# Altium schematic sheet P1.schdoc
size 127 x 101 mm
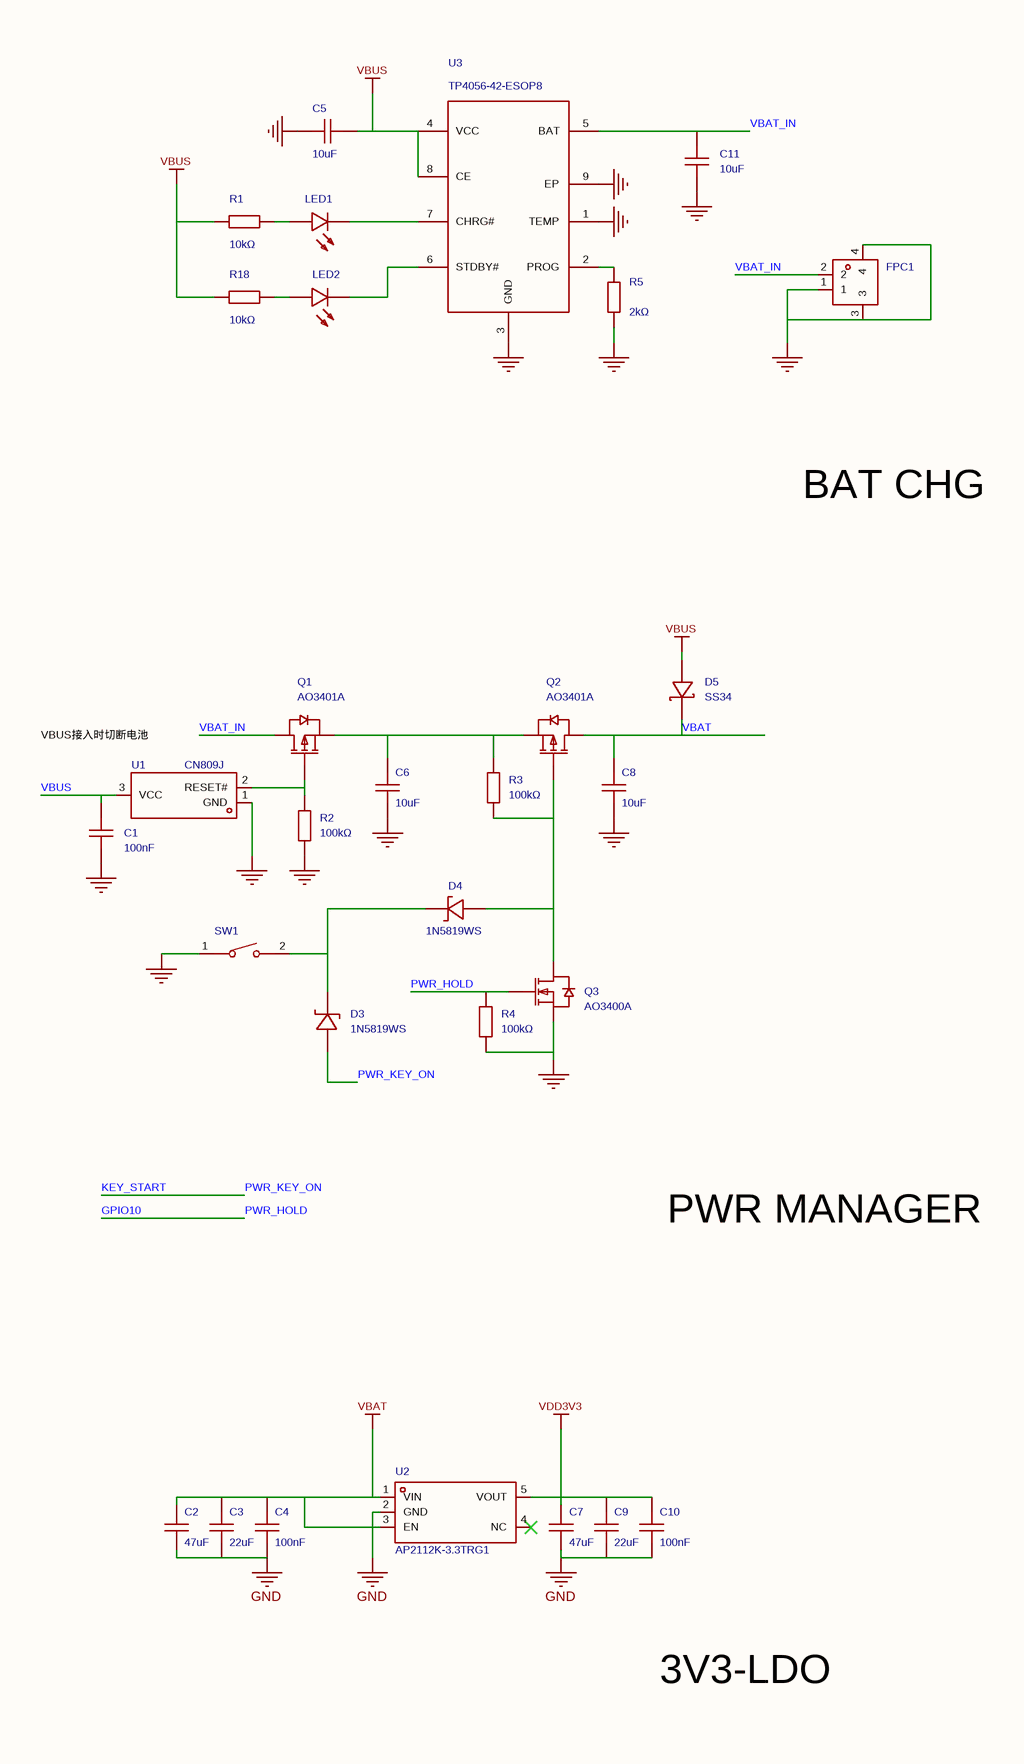
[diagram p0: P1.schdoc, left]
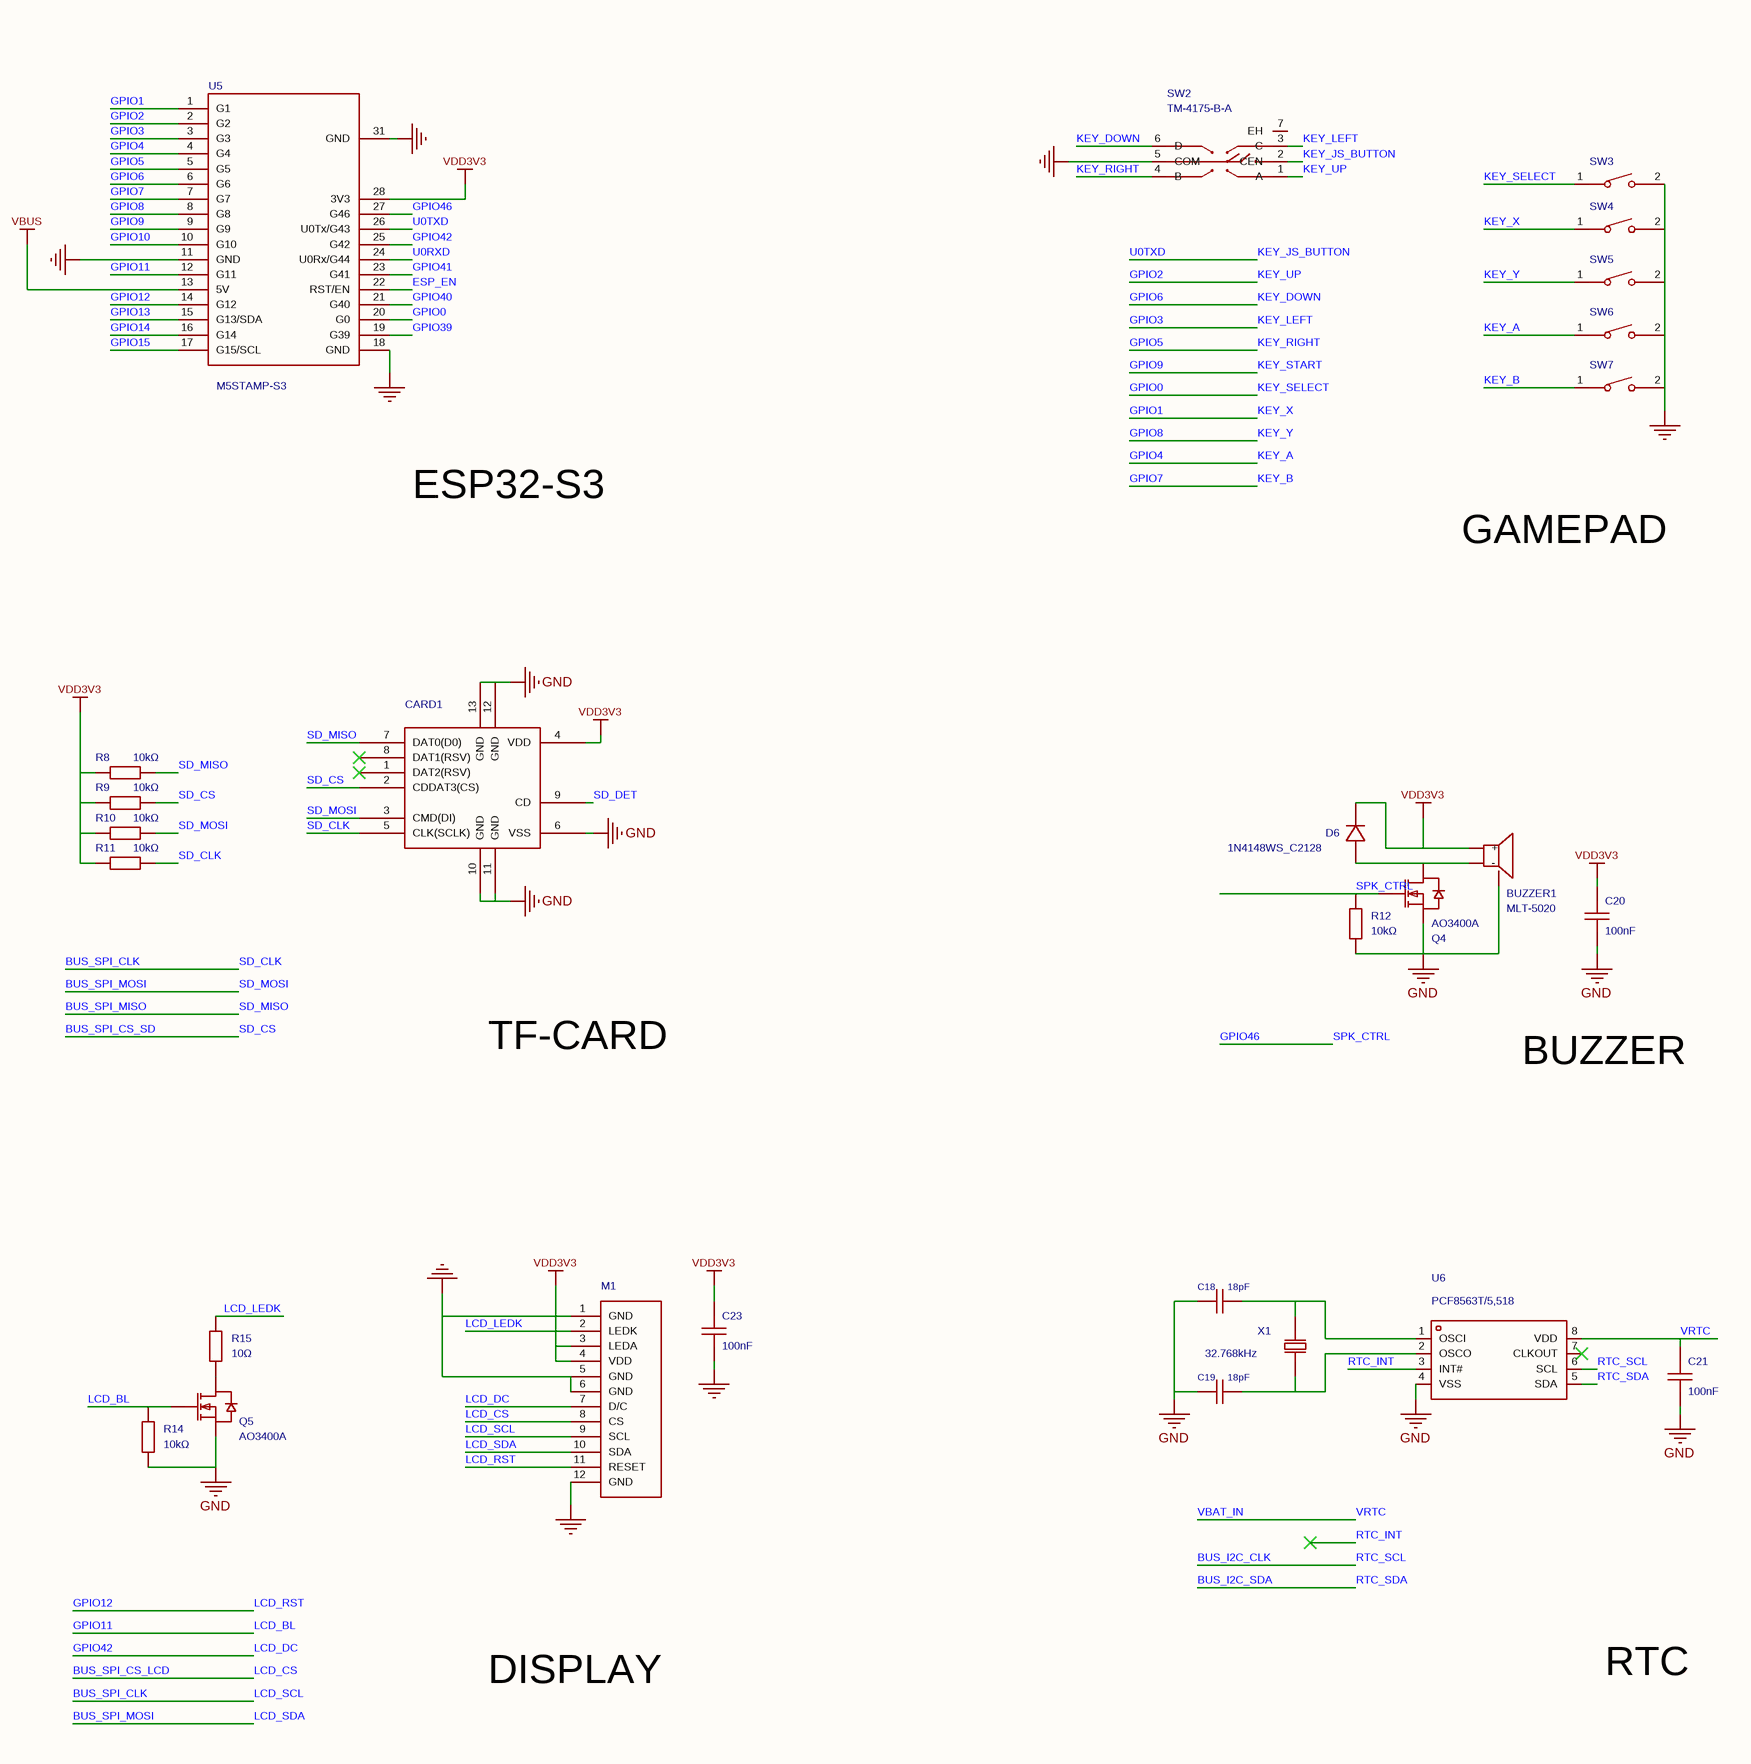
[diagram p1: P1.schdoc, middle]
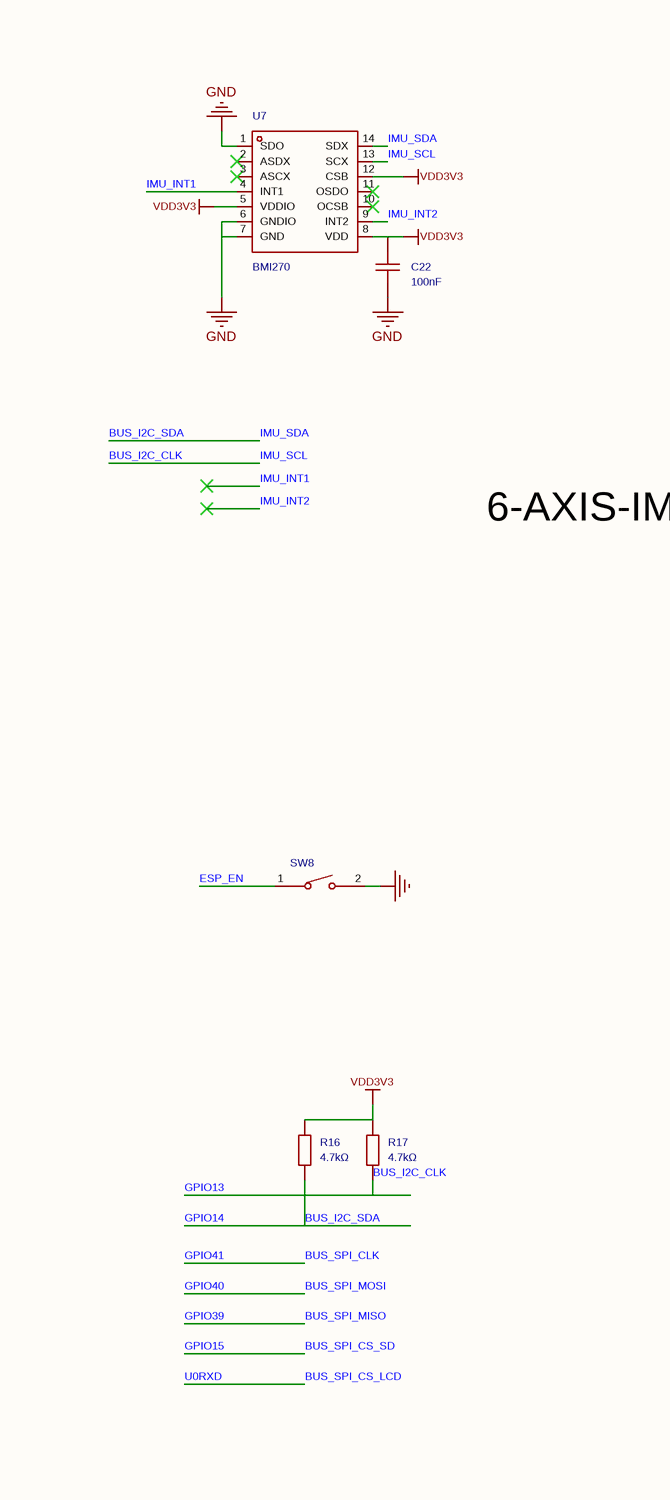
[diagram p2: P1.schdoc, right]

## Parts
BUZZER1  4000Hz  [BUZ-SMD_L5.0-W5.5-P4.60]  (value not drawn)
C1  100nF  [C0603]
C2  47uF  [C0805]
C3  22uF  [C0805]
C4  100nF  [C0603]
C5  10uF  [C0603]
C6  10uF  [C0603]
C7  47uF  [C0805]
C8  10uF  [C0603]
C9  22uF  [C0805]
C10  100nF  [C0603]
C11  10uF  [C0603]
C18  18pF  [C0603]
C19  18pF  [C0603]
C20  100nF  [C0603]
C21  100nF  [C0603]
C22  100nF  [C0603]
C23  100nF  [C0603]
CARD1  (no value)  [TF-SMD_TF-01A]
D3  1N5819WS  [SOD-323_L1.8-W1.3-LS2.5-RD]
D4  1N5819WS  [SOD-323_L1.8-W1.3-LS2.5-RD]
D5  SS34  [SMA_L4.3-W2.6-LS5.2-RD]
D6  1N4148WS  [SOD-323_L1.8-W1.3-LS2.5-RD]  (value not drawn)
FPC1  1.25-2PWB  [CONN-SMD_2P-P1.25_DEALON_1.25-2PWB]  (value not drawn)
LED1  19-213/Y2C-CQ2R2L/3T(CY)  [LED0603-RD-YELLOW]  (value not drawn)
LED2  19-217/GHC-YR1S2/3T  [LED0603-RD]  (value not drawn)
M1  1.3寸TFT240*240  [1.3寸TFT240_240]  (value not drawn)
Q1  AO3401A  [SOT-23_L2.9-W1.3-P1.90-LS2.4-BR]
Q2  AO3401A  [SOT-23_L2.9-W1.3-P1.90-LS2.4-BR]
Q3  AO3400A  [sot-23_l2.9-w1.3-p1.90-ls2.4-br]
Q4  AO3400A  [sot-23_l2.9-w1.3-p1.90-ls2.4-br]
Q5  AO3400A  [sot-23_l2.9-w1.3-p1.90-ls2.4-br]
R1  10kΩ  [R0603]
R2  100kΩ  [R0603]
R3  100kΩ  [R0603]
R4  100kΩ  [R0603]
R5  2kΩ  [R0603]
R8  10kΩ  [R0603]
R9  10kΩ  [R0603]
R10  10kΩ  [R0603]
R11  10kΩ  [R0603]
R12  10kΩ  [R0603]
R14  10kΩ  [R0603]
R15  10Ω  [R0603]
R16  4.7kΩ  [R0603]
R17  4.7kΩ  [R0603]
R18  10kΩ  [R0603]
SW1  TS-1088-AR02016  [SW-SMD_L3.9-W3.0-P4.45]  (value not drawn)
SW2  TM-4175-B-A  [SW-SMD_TM-4175-B-X]
SW3  TS-1088-AR02016  [SW-SMD_L3.9-W3.0-P4.45]  (value not drawn)
SW4  TS-1088-AR02016  [SW-SMD_L3.9-W3.0-P4.45]  (value not drawn)
SW5  TS-1088-AR02016  [SW-SMD_L3.9-W3.0-P4.45]  (value not drawn)
SW6  TS-1088-AR02016  [SW-SMD_L3.9-W3.0-P4.45]  (value not drawn)
SW7  TS-1088-AR02016  [SW-SMD_L3.9-W3.0-P4.45]  (value not drawn)
SW8  TS-1088-AR02016  [SW-SMD_L3.9-W3.0-P4.45]  (value not drawn)
U1  CN809J  [SOT-23-3_L2.9-W1.3-P1.90-LS2.4-BR]
U2  AP2112K-3.3TRG1  [SOT-25-5_L3.0-W1.8-P0.95-LS3.0-BR]
U3  TP4056-42-ESOP8  [ESOP-8_L4.9-W3.9-P1.27-LS6.0-BL-EP]
U5  M5STAMP-S3  [STAMP-S3-PIN-SMD]
U6  PCF8563T/5,518  [SOIC-8_L5.0-W4.0-P1.27-LS6.0-BL]
U7  BMI270  [LGA-14_L3.0-W2.5-P0.50-BR]
X1  32.768kHz  [FC-135R_L3.2-W1.5]

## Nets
GND: BUZZER1.3(NC) C1.1 C2.1 C3.1 C4.1 C5.2 C6.1 C7.1 C8.1 C9.1 C10.1 C11.1 C18.1 C19.1 C20.1 C21.1 C22.1 C23.1 CARD1.6(VSS) CARD1.10(GND) CARD1.11(GND) CARD1.12(GND) CARD1.13(GND) FPC1.1 FPC1.3 FPC1.4 M1.1(GND) M1.5(GND) M1.6(GND) M1.12(GND) Q3.2(S) Q4.2(S) Q5.2(S) R2.1 R4.1 R5.1 R12.2 R14.2 SW1.1 SW2.5(COM) SW3.2 SW4.2 SW5.2 SW6.2 SW7.2 SW8.2 U1.1(GND) U2.2(GND) U3.1(TEMP) U3.3(GND) U3.9(EP) U5.11(GND) U5.18(GND) U5.31(GND) U6.4(VSS) U7.1(SDO) U7.6(GNDIO) U7.7(GND)
VBAT: C2.2 C3.2 C4.2 C8.2 D5.1(K) Q2.3(D) U2.1(VIN) U2.3(EN)
VBUS: C1.2 C5.1 D5.2(A) R1.1 R18.1 U1.3(VCC) U3.4(VCC) U3.8(CE) U5.13(5V)
VDD3V3: BUZZER1.1(+) C7.2 C9.2 C10.2 C20.2 C22.2 C23.2 CARD1.4(VDD) D6.1(K) M1.3(LEDA) M1.4(VDD) R8.2 R9.2 R10.2 R11.2 R16.2 R17.2 U2.5(VOUT) U5.28(3V3) U7.5(VDDIO) U7.8(VDD) U7.12(CSB)
BUS_I2C_CLK: R17.1 U5.15(G13/SDA) U6.6(SCL) U7.13(SCX)  [also labelled GPIO13, IMU_SCL, RTC_SCL]
BUS_I2C_SDA: R16.1 U5.16(G14) U6.5(SDA) U7.14(SDX)  [also labelled GPIO14, IMU_SDA, RTC_SDA]
BUS_SPI_CLK: CARD1.5(CLK(SCLK)) M1.9(SCL) R11.1 U5.23(G41)  [also labelled GPIO41, LCD_SCL, SD_CLK]
BUS_SPI_CS_LCD: M1.8(CS) U5.24(U0Rx/G44)  [also labelled LCD_CS, U0RXD]
BUS_SPI_CS_SD: CARD1.2(CDDAT3(CS)) R9.1 U5.17(G15/SCL)  [also labelled GPIO15, SD_CS]
BUS_SPI_MISO: CARD1.7(DAT0(D0)) R8.1 U5.19(G39)  [also labelled GPIO39, SD_MISO]
BUS_SPI_MOSI: CARD1.3(CMD(DI)) M1.10(SDA) R10.1 U5.21(G40)  [also labelled GPIO40, LCD_SDA, SD_MOSI]
ESP_EN: SW8.1 U5.22(RST/EN)
GPIO0: SW3.1 U5.20(G0)  [also labelled KEY_SELECT]
GPIO1: SW4.1 U5.1(G1)  [also labelled KEY_X]
GPIO2: SW2.1(A) U5.2(G2)  [also labelled KEY_UP]
GPIO3: SW2.3(C) U5.3(G3)  [also labelled KEY_LEFT]
GPIO4: SW6.1 U5.4(G4)  [also labelled KEY_A]
GPIO5: SW2.4(B) U5.5(G5)  [also labelled KEY_RIGHT]
GPIO6: SW2.6(D) U5.6(G6)  [also labelled KEY_DOWN]
GPIO7: SW7.1 U5.7(G7)  [also labelled KEY_B]
GPIO8: SW5.1 U5.8(G8)  [also labelled KEY_Y]
GPIO9: D3.2(A) U5.9(G9)  [also labelled KEY_START, PWR_KEY_ON]
GPIO10: Q3.1(G) R4.2 U5.10(G10)  [also labelled PWR_HOLD]
GPIO11: Q5.1(G) R14.1 U5.12(G11)  [also labelled LCD_BL]
GPIO12: M1.11(RESET) U5.14(G12)  [also labelled LCD_RST]
GPIO42: M1.7(D/C) U5.25(G42)  [also labelled LCD_DC]
GPIO46: Q4.1(G) R12.1 U5.27(G46)  [also labelled SPK_CTRL]
IMU_INT1: U7.4(INT1)
IMU_INT2: U7.9(INT2)
KEY_JS_BUTTON: SW2.2(CEN) U5.26(U0Tx/G43)  [also labelled U0TXD]
LCD_LEDK: M1.2(LEDK) R15.2
RTC_INT: U6.3(INT#)
SD_DET: CARD1.9(CD)
VBAT_IN: C11.2 C21.2 FPC1.2 Q1.3(D) U3.5(BAT) U6.8(VDD)  [also labelled VRTC]
NetBUZZER1_2: BUZZER1.2(-) D6.2(A) Q4.3(D)
NetC6_2: C6.2 Q1.2(S) Q2.2(S) R3.2
NetC18_2: C18.2 U6.1(OSCI) X1.1
NetC19_2: C19.2 U6.2(OSCO) X1.2
NetD3_1: D3.1(C) D4.1(C) SW1.2
NetD4_2: D4.2(A) Q2.1(G) Q3.3(D) R3.1
NetLED1_1: LED1.1(C) U3.7(CHRG#)
NetLED1_2: LED1.2(A) R1.2
NetLED2_1: LED2.1(C) U3.6(STDBY#)
NetLED2_2: LED2.2(A) R18.2
NetQ1_1: Q1.1(G) R2.2 U1.2(RESET#)
NetQ5_3: Q5.3(D) R15.1
NetR5_2: R5.2 U3.2(PROG)

Not connected (* = marked no-connect by the designer): CARD1 1(DAT2(RSV))* 8(DAT1(RSV))*; SW2 7(EH); U2 4(NC)*; U6 7(CLKOUT)*; U7 2(ASDX)* 3(ASCX)* 10(OCSB)* 11(OSDO)*

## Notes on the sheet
- BAT CHG
- ESP32-S3
- GAMEPAD
- 6-AXIS-IMU
- VBUS接入时切断电池
- TF-CARD
- BUZZER
- PWR MANAGER
- 3V3-LDO
- DISPLAY
- RTC

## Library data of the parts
BUZZER1 = MLT-5020: 驱动方式:无源(外部驱动);构造类型:电磁式;频率:4000Hz;长度:5.2mm;宽度:5.2mm;高度:2.5mm;; Manufacturer: 华能; AddInBom: yes; ModelId: 0044e78390e14de39818311c3b0a8804; ModelName: BUZ-SMD_3P-L5.2-W5.2-H2.0-P3.50; ModelTransform: 207.31557,204.724,0,270,0,0,-0.001,0.003,0; Technology Type: 电磁式
C1 C4 C10 C20-C23 = CC0603KRX7R9BB104: 容值:100nF;精度:±10%;额定电压:50V;材质(温度系数):X7R;; Manufacturer: YAGEO(国巨); AddInBom: yes; ModelId: ac125912035d415993ca9572d50418b1; ModelName: C0603_L1.6-W0.8-H0.8; ModelTransform: 62.992,31.496,0,0,0,0,0,0,0; Tolerance: ±10%; Voltage Rated: 50V; Temperature Coefficient: X7R
C2 C7 = CL21A476MQYNNNE: 容值:47uF;精度:±20%;额定电压:6.3V;材质(温度系数):X5R;; Manufacturer: SAMSUNG(三星); AddInBom: yes; ModelId: 1ba041120af144c991958decab20d241; ModelName: C0805_L2.0-W1.3-H1.3; ModelTransform: 78.74,51.181,0,0,0,0,0,0.0005,0; Tolerance: ±20%; Voltage Rated: 6.3V; Temperature Coefficient: X5R
C3 C9 = CL21A226MAQNNNE_C45783: 容值:22uF;精度:±20%;额定电压:25V;材质(温度系数):X5R;; Manufacturer: SAMSUNG(三星); AddInBom: yes; ModelId: 1ba041120af144c991958decab20d241; ModelName: C0805_L2.0-W1.3-H1.3; ModelTransform: 78.74,51.181,0,0,0,0,0,0.0005,0; Tolerance: ±20%; Voltage Rated: 25V; Temperature Coefficient: X5R
C5 C6 C8 C11 = CL10A106KP8NNNC: 容值:10uF;精度:±10%;额定电压:10V;材质(温度系数):X5R;; Manufacturer: SAMSUNG(三星); AddInBom: yes; ModelId: ac125912035d415993ca9572d50418b1; ModelName: C0603_L1.6-W0.8-H0.8; ModelTransform: 62.992,31.496,0,0,0,0,0,0,0; Tolerance: ±10%; Voltage Rated: 10V; Temperature Coefficient: X5R
C18 C19 = CL10C180JB8NNNC: 温度系数:C0G;容值:18pF;精度:±5%;额定电压:50V;; Manufacturer: SAMSUNG(三星); AddInBom: yes; ModelId: ac125912035d415993ca9572d50418b1; ModelName: C0603_L1.6-W0.8-H0.8; ModelTransform: 62.992,31.496,0,0,0,0,0,0,0; Temperature Coefficient: C0G; Tolerance: ±5%; Voltage Rated: 50V
CARD1 = TF-01A: 卡连接方式:自弹式;卡类型:MicroSD卡(TF卡);连接器类型:卡座;本体最大高度:-;触头材质:-;触头镀层:-;工作温度范围:-;焊接温度(最大值):-;; Manufacturer: 韩国韩荣; AddInBom: yes; ModelId: 5b4be50223494db9bf5c92b2cb3c1375; ModelName: TF-SMD_L14.8-W14.5-H1.9-P1.1; ModelTransform: 629.92,600.393,0,0,0,0,0,-85.473,-23.622; Card Connection Mode: 自弹式; Connector Type: 卡座
D3 D4 = 1N5819WS_C191023: 直流反向耐压(Vr):40V;平均整流电流(Io):1A;正向压降(Vf):600mV@1A;; Manufacturer: Hottech(合科泰); AddInBom: yes; ModelId: e9dd044ee7bf4221b3b795eb56bce7c0; ModelName: SOD-323_L1.7-W1.3-H1.1-LS2.5; ModelTransform: 98.91933,51.181,0,180,0,0,0.985,-0.0005,0; Reverse Voltage (Vr): 40V; Average Rectified Current (Io): 1A
D5 = SS34_C8678: 二极管配置:独立式;直流反向耐压(Vr):40V;平均整流电流(Io):3A;正向压降(Vf):550mV@3A;; Manufacturer: MDD; AddInBom: yes; ModelId: 7ed2c9d0a4a74bbdbba07ab4052caf5b; ModelTransform: 185.039,102.362,0,0,0,0,0,0,0; Diode Configuration: 独立式; Reverse Voltage (Vr): 40V; Average Rectified Current (Io): 3A; Reverse Leakage Current (Ir): 500uA@40V
D6 = 1N4148WS_C2128: 二极管配置:独立式;功率:200mW;直流反向耐压(Vr):100V;平均整流电流(Io):150mA;正向压降(Vf):1.25V@150mA;反向电流(Ir):1uA@75V;反向恢复时间(trr):4ns;工作温度:+150℃@(Tj);; Manufacturer: CJ(江苏长电/长晶); Symbol: 1N4148WS T4; AddInBom: yes; ModelId: e9dd044ee7bf4221b3b795eb56bce7c0; ModelName: SOD-323_L1.7-W1.3-H1.1-LS2.5; ModelTransform: 98.91933,51.181,0,180,0,0,0.985,-0.0005,0; Diode Configuration: 独立式; Power Dissipation: 200mW; Reverse Voltage (Vr): 100V; Average Rectified Current (Io): 150mA; Reverse Recovery Time (trr): 4ns
FPC1 = 1.25-2PWB: 参考系列:-;间距:1.25mm;插针结构:1x2P;排数:1;每排PIN数:2;行距:-;公母:公型插针;安装方式:卧贴;额定电流:-;工作温度范围:-40℃~+85℃;; Manufacturer: DEALON(德艺隆); AddInBom: yes; ModelId: 9acbac5bbda042939c64ce5e8a61b6c2; ModelTransform: 285.4325,206.693,0,180,0,0,0,-36.85,0; Pitch: 1.25mm; Pins Structure: 1x2P; Number of PINs Per Row: 2; Gender: 公型插针
LED1 = 19-213/Y2C-CQ2R2L/3T(CY): 发光颜色:黄灯;二极管配置:-;主波长:585.5nm~591.5nm;色温:-;功率:60mW;安装方式:-;; Manufacturer: EVERLIGHT(亿光); AddInBom: yes; ModelId: a8fc7d5425514cf49dd600af0a7bb223; ModelTransform: 63.7794,32.283,0,0,0,0,-1.969,0,0; Emitted Color: 黄灯; Lens Color: 无色透明; Peak Wavelength: 591nm; Forward Current: 20mA; Power Dissipation: 60mW; Viewing Angle: 120°
LED2 = 19-217/GHC-YR1S2/3T: 发光颜色:翠绿;二极管配置:-;透镜颜色:无色透明;主波长:520nm~535nm;色温:-;发光强度:199mcd;功率:110mW;发光角度:120°;安装方式:-;工作温度:-40℃~+85℃;; Manufacturer: EVERLIGHT(亿光); AddInBom: yes; ModelId: 1f0d29a91be547639d425604e9b96ebb; ModelTransform: 63.7794,32.283,0,0,0,0,0,0,0; Emitted Color: 翠绿; Lens Color: 无色透明; Peak Wavelength: 518nm; Forward Current: 20mA; Forward Voltage (VF): 3.3V; Luminous Intensity: 199mcd; Power Dissipation: 110mW; Viewing Angle: 120°
M1 = 1.3寸TFT240*240: AddInBom: yes
Q1 Q2 = AO3401A_C15127: 类型:P沟道;漏源电压(Vdss):30V;连续漏极电流(Id):4A;功率(Pd):1.4W;导通电阻(RDS(on)@Vgs,Id):44mΩ@10V,4.3A;; Manufacturer: AOS; AddInBom: yes; ModelId: c62791f0466c4ae2a892c056b845b0ca; ModelName: SOT-23-3P_L2.9-W1.3-H1.0-LS2.4-P0.95; ModelTransform: 98.64468,114.173,0,180,0,0,0,0,0; Type: P沟道; Drain Source Voltage (Vdss): 30V; Continuous Drain Current (Id): 4A; Power Dissipation (Pd): 1.4W; Gate Threshold Voltage (Vgs(th)@Id): 1.3V@250uA
Q3-Q5 = AO3400A_C20917: 类型:N沟道;漏源电压(Vdss):30V;连续漏极电流(Id):5.7A;功率(Pd):1.4W;导通电阻(RDS(on)@Vgs,Id):26.5mΩ@10V,5.7A;; Manufacturer: AOS; AddInBom: yes; ModelId: 89cb27a44ab2466697082bb9fd73a7d0; ModelName: SOT-23-3L_L2.9-W1.6-H1.1-LS2.8-P0.95; ModelTransform: 110.236,114.173,0,180,0,0,-0.005,0.0005,0; Type: N沟道; Drain Source Voltage (Vdss): 30V; Power Dissipation (Pd): 1.4W; Gate Threshold Voltage (Vgs(th)@Id): 1.5V@250uA
R1 R8-R12 R14 R18 = 0603WAF1002T5E: 电阻类型:厚膜电阻;阻值:10kΩ;精度:±1%;功率:100mW;; Manufacturer: UNI-ROYAL(厚声); AddInBom: yes; ModelId: fc143cca1e79419f9cd78b61e9279f08; ModelTransform: 31.8897,63.7794,0,90,0,0,0,0,0; Tolerance: ±1%; Power(Watts): 100mW; Temperature Coefficient: ±100ppm/℃; Overload Voltage (Max): 75V
R2-R4 = 0603WAF1003T5E: 电阻类型:厚膜电阻;阻值:100kΩ;精度:±1%;功率:100mW;; Manufacturer: UNI-ROYAL(厚声); AddInBom: yes; ModelId: fc143cca1e79419f9cd78b61e9279f08; ModelTransform: 31.8897,63.7794,0,90,0,0,0,0,0; Tolerance: ±1%; Power(Watts): 100mW; Temperature Coefficient: ±100ppm/℃; Overload Voltage (Max): 75V
R5 = 0603WAF2001T5E: 电阻类型:厚膜电阻;阻值:2kΩ;精度:±1%;功率:100mW;; Manufacturer: UNI-ROYAL(厚声); AddInBom: yes; ModelId: fc143cca1e79419f9cd78b61e9279f08; ModelTransform: 31.8897,63.7794,0,90,0,0,0,0,0; Tolerance: ±1%; Power(Watts): 100mW; Temperature Coefficient: ±100ppm/℃; Overload Voltage (Max): 75V
R15 = 0603WAF100JT5E: 电阻类型:厚膜电阻;阻值:10Ω;精度:±1%;功率:100mW;温度系数:±400ppm/℃;最大工作电压:75V;工作温度范围:-55℃~+155℃;; Manufacturer: UNI-ROYAL(厚声); AddInBom: yes; ModelId: 3281a289d46d4bb1877be1eabd090e13; ModelName: R0603_L1.6-W0.8-H0.8; ModelTransform: 62.992,31.496,0,0,0,0,0,0,0; Tolerance: ±1%; Power(Watts): 100mW; Overload Voltage (Max): 75V
R16 R17 = 0603WAF4701T5E: 电阻类型:厚膜电阻;阻值:4.7kΩ;精度:±1%;功率:100mW;; Manufacturer: UNI-ROYAL(厚声); AddInBom: yes; ModelId: fc143cca1e79419f9cd78b61e9279f08; ModelTransform: 31.8897,63.7794,0,90,0,0,0,0,0; Tolerance: ±1%; Power(Watts): 100mW; Temperature Coefficient: ±100ppm/℃; Overload Voltage (Max): 75V
SW1 SW3-SW8 = TS-1088-AR02016: 触点电流:50mA;额定电压(DC):12V;绝缘电阻:100MΩ;电路结构:单刀单掷;安装方式:立贴;作用力:160gf@±50gf;机械寿命:10万次;带支架:否;; Manufacturer: XUNPU(讯普); AddInBom: yes; ModelId: b26698b69f274ffabef8a26c7d0e5dd1; ModelName: SW-SMD_L3.9-W2.9-H2.0-LS4.8; ModelTransform: 188.976,114.174,0,0,0,0,0,0,0; Contact Current: 50mA; Voltage Rating (DC): 12V; Insulation Resistance: 100MΩ; Circuit: 单刀单掷; Actuator Style: 圆形按钮; Actuator/Cap Color: 黑色; Mechanical Life: 10万次; Pin Style: SMD接片; Switch Length: 4mm; Switch Width: 3mm; Switch Height: 2mm; Strike Gundam: 否
SW2 = TM-4175-B-A: 多功能开关 7.5*7.5*5 五向开关 H5; Manufacturer: XKB Connectivity(中国星坤); AddInBom: yes; ModelId: fa03cf810e604d4192717ee228c97197; ModelTransform: 295.275,334.645,0,0,0,0,-0.005,0,-19.685
U1 = CN809J: 电源管理芯片的类型:-;监控的组数:-;输出端类型:-;有效的复位电平:-;复位阀值电压:-;; Manufacturer: CONSONANCE(上海如韵); AddInBom: yes; ModelId: c62791f0466c4ae2a892c056b845b0ca; ModelName: SOT-23-3P_L2.9-W1.3-H1.0-LS2.4-P0.95; ModelTransform: 98.425,114.173,0,180,0,0,0.0005,-0.0005,0
U2 = AP2112K-3.3TRG1: 输出类型:固定;输出极性:正;输出通道数:1;最大输入电压:6V;输出电压:3.3V;压差:400mV@(600mA);输出电流:600mA;电源纹波抑制比(PSRR):65dB@(100Hz,1kHz);; Manufacturer: DIODES(美台); AddInBom: yes; ModelId: 2af5e521bdd54ca3a4af644424b5a864; ModelName: SOT-25-5_L3.0-W1.6-H1.3-LS2.8-P0.95; ModelTransform: 110.7,118.1,0,180,0,0,-2.5,2.5,0; Output Type: 固定; Output Polarity: 正; Number of Outputs: 1; Maximum Input Voltage: 6V; Output Voltage: 3.3V
U3 = TP4056-42-ESOP8: 锂电池充电芯片; Manufacturer: TOPPOWER(南京拓微); Symbol: TP4056; AddInBom: yes; ModelId: d3e00daa36c445139c055a3b9efb85d2; ModelName: ESOP-8_L4.9-W3.9-H1.6-LS6.0-P1.27; ModelTransform: 240.157,192.913,0,90,0,0,0,0,0
U5 = STAMP-S3-PIN-SMD: AddInBom: yes; ModelId: 5fd44e0520a141d1948b25da1d6120b7; ModelName: M5STAMP-S3_v0.1_2022-10-13; ModelTransform: 708.61,1021.5,257.43,0,0,0,0,-38.19,-77.56
U6 = PCF8563T/5,518: 接口:I2C;; Manufacturer: NXP(恩智浦); AddInBom: yes; ModelId: e81d2f7d937b4a6ab1dca543ff5d56a4; ModelName: SOIC-8_L4.9-W3.9-H1.7-LS6.0-P1.27; ModelTransform: 189.751,236.22,0,0,0,0,-0.0005,0.0005,0; Interface: I2C; Operating Voltage: 1.8V~5.5V
U7 = BMI270: IMU-惯性测量单元; Manufacturer: Bosch(博世); AddInBom: yes; ModelId: 64f32784a16f466f897e9e56b6bbdf45; ModelTransform: 118.11,98.425,0,180,0,0,-0.002,0.004,0
X1 = Q13FC1350000400: 晶振类型:贴片无源晶振;频率:32.768kHz;频率公差:±20ppm;负载电容:12.5pF;等效串联电阻(ESR):70kΩ;工作温度:-40℃~+85℃;; Manufacturer: EPSON(爱普生); AddInBom: yes; ModelId: b5334dc599ac49d68fb741bd067a525d; ModelName: SMD-3215_2P_L3.2-W1.5-H0.8; ModelTransform: 125.984,59.055,0,0,0,0,0,0,0; Crystal Type: 贴片无源晶振; Frequency Tolerance: ±20ppm; Load Capacitance: 12.5pF; Equivalent Series Resistance (ESR): 70kΩ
